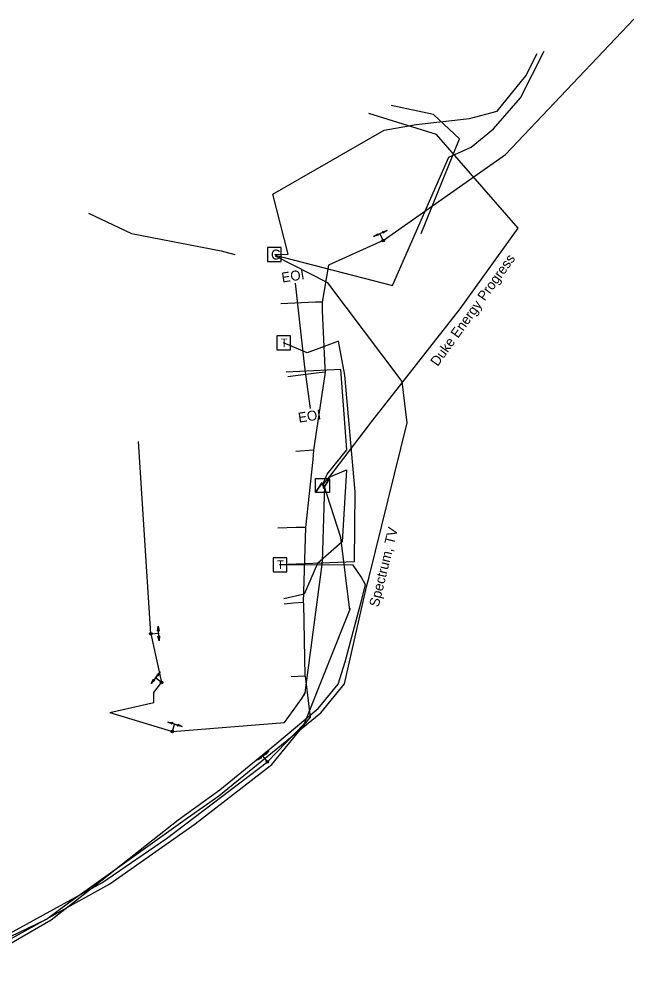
# Model space of a CAD drawing. Extents: x 2070721 to 2083340, y 729290 to 737883.
# Drawn here: x 2080279.4 to 2080526.8, y 734985.4 to 735370.3 of the extents above; entities that cross this region are included whole.
import ezdxf

# ---------------------------------------------------------------- set-up
doc = ezdxf.new("R2010")
doc.units = 0
for name, color, linetype in [('Exist Utilities Gas Change of Service SUE CELL', 7, 'Continuous'), ('Exist Utilities Gas UG Line SUE LOS B', 7, 'Continuous'), ('Exist Utilities Gas UG Line SUE LOS C', 7, 'Continuous'), ('Exist Utilities Other Pole Text', 7, 'Continuous'), ('Exist Utilities Other Unknown UG SUE LOS B', 7, 'Continuous'), ('Exist Utilities Power Change of Service SUE CELL', 7, 'Continuous'), ('Exist Utilities Power Transformer CELL', 7, 'Continuous'), ('Exist Utilities Power UG Cable SUE LOS B', 7, 'Continuous'), ('Exist Utilities Power UG Cable SUE LOS B Text', 7, 'Continuous'), ('Exist Utilities Power UG Cable SUE LOS C', 7, 'Continuous'), ('Exist Utilities Telephone Pedestal CELL', 7, 'Continuous'), ('Exist Utilities Telephone UG Cable SUE LOS C', 7, 'Continuous'), ('Exist Utilities TV Pedestal CELL', 7, 'Continuous'), ('Exist Utilities TV UG Cable SUE LOS C', 7, 'Continuous'), ('Exist Utilities TV UG Cable SUE LOS C Text', 7, 'Continuous'), ('Exist Utilities Water UG Line SUE LOS B', 7, 'Continuous')]:
    doc.layers.add(name, color=color, linetype=linetype)

msp = doc.modelspace()

# ---------------------------------------------------------------- linework, layer by layer
at = {"layer": 'Exist Utilities Gas Change of Service SUE CELL'}
for p, q in [((2080427.49, 735285.18), (2080422.06, 735282.72)), ((2080424.64, 735283.89), (2080427.49, 735285.18)), ((2080425.91, 735281.08), (2080424.64, 735283.89)), ((2080425.91, 735281.08), (2080425.91, 735281.08))]:
    msp.add_line(p, q, dxfattribs=at)
for points in [[(2080422.06, 735282.72), (2080423.71, 735283.85), (2080423.47, 735283.36), (2080423.95, 735283.24)], [(2080427.49, 735285.18), (2080425.84, 735284.06), (2080426.08, 735284.54), (2080425.61, 735284.67)]]:
    msp.add_lwpolyline(points, close=True, dxfattribs=at)
msp.add_circle((2080425.91, 735281.08), 0.517, dxfattribs=at)
at = {"layer": 'Exist Utilities Gas UG Line SUE LOS B'}
msp.add_line((2080397.88, 735196.69), (2080390.75, 735196.19), dxfattribs=at)
for points in [[(2080425.91, 735281.08), (2080403.96, 735271.14), (2080401.43, 735256.34)], [(2080401.43, 735256.34), (2080398.73, 735256.24), (2080384.69, 735255.67)], [(2080401.43, 735256.34), (2080401.37, 735252.76), (2080402.5, 735229.83), (2080402.55, 735228.15)], [(2080402.55, 735228.15), (2080399.01, 735227.73), (2080387.55, 735226.22)], [(2080402.55, 735228.15), (2080397.88, 735196.69)], [(2080397.88, 735196.69), (2080397.62, 735192.92), (2080394.69, 735165.62)], [(2080394.69, 735165.62), (2080390.87, 735165.52), (2080383.56, 735165.33)], [(2080394.7, 735165.52), (2080393.67, 735135.42)], [(2080393.67, 735135.42), (2080389.85, 735135.05), (2080386.03, 735134.67)], [(2080393.67, 735135.42), (2080393.83, 735134.93), (2080394.41, 735105.63), (2080388.9, 735105.46)], [(2080265, 734993.65), (2080268.16, 734995.62), (2080315.96, 735022.08), (2080350.22, 735046.21), (2080381.14, 735070.17), (2080396.65, 735089.25), (2080394.64, 735105.68)]]:
    msp.add_lwpolyline(points, dxfattribs=at)
at = {"layer": 'Exist Utilities Gas UG Line SUE LOS C'}
msp.add_lwpolyline([(2080425.91, 735281.08), (2080475.14, 735315.78), (2080526.82, 735370.27)], dxfattribs=at)
at = {"layer": 'Exist Utilities Other Unknown UG SUE LOS B'}
msp.add_lwpolyline([(2080390.53, 735263.96), (2080394.31, 735230.13), (2080396.49, 735213.47)], dxfattribs=at)
at = {"layer": 'Exist Utilities Power Change of Service SUE CELL'}
for p, q in [((2080335.71, 735119.86), (2080335.33, 735125.81)), ((2080332.43, 735122.8), (2080335.51, 735122.99)), ((2080332.43, 735122.8), (2080332.43, 735122.8)), ((2080335.51, 735122.99), (2080335.71, 735119.86)), ((2080336.21, 735107.48), (2080332.59, 735102.74)), ((2080334.31, 735104.99), (2080336.21, 735107.48)), ((2080336.76, 735103.12), (2080334.31, 735104.99)), ((2080336.76, 735103.12), (2080336.76, 735103.12)), ((2080344.98, 735085.47), (2080339.28, 735087.21)), ((2080341.08, 735083.44), (2080341.98, 735086.39)), ((2080341.08, 735083.44), (2080341.08, 735083.44)), ((2080341.98, 735086.39), (2080344.98, 735085.47)), ((2080379.95, 735075.53), (2080375.2, 735071.92)), ((2080377.45, 735073.63), (2080379.95, 735075.53)), ((2080379.32, 735071.17), (2080377.45, 735073.63)), ((2080379.32, 735071.17), (2080379.32, 735071.17))]:
    msp.add_line(p, q, dxfattribs=at)
for points in [[(2080335.33, 735125.81), (2080335.8, 735123.87), (2080335.43, 735124.27), (2080335.15, 735123.87)], [(2080335.71, 735119.86), (2080335.24, 735121.81), (2080335.61, 735121.41), (2080335.89, 735121.81)], [(2080336.21, 735107.48), (2080335.29, 735105.71), (2080335.27, 735106.25), (2080334.79, 735106.13)], [(2080332.59, 735102.74), (2080333.51, 735104.52), (2080333.53, 735103.97), (2080334.01, 735104.09)], [(2080339.28, 735087.21), (2080341.27, 735086.97), (2080340.76, 735086.76), (2080341.04, 735086.36)], [(2080344.98, 735085.47), (2080343, 735085.72), (2080343.5, 735085.93), (2080343.22, 735086.33)], [(2080379.95, 735075.53), (2080378.59, 735074.06), (2080378.72, 735074.59), (2080378.23, 735074.6)], [(2080375.2, 735071.92), (2080376.56, 735073.39), (2080376.44, 735072.86), (2080376.93, 735072.85)]]:
    msp.add_lwpolyline(points, close=True, dxfattribs=at)
for centre in [(2080332.43, 735122.8), (2080336.76, 735103.12), (2080341.08, 735083.44), (2080379.32, 735071.17)]:
    msp.add_circle(centre, 0.517, dxfattribs=at)
at = {"layer": 'Exist Utilities Power Transformer CELL'}
msp.add_line((2080401.57, 735182.62), (2080401.57, 735182.62), dxfattribs=at)
msp.add_lwpolyline([(2080398.72, 735185.24), (2080404.27, 735185.24), (2080404.27, 735179.68), (2080398.72, 735179.68)], close=True, dxfattribs=at)
for points in [[(2080398.72, 735179.68), (2080401.37, 735183.63), (2080401.99, 735181.42), (2080404.27, 735185.24)], [(2080398.79, 735179.68), (2080401.37, 735183.42), (2080401.95, 735181.24), (2080404.27, 735185.08)]]:
    msp.add_lwpolyline(points, dxfattribs=at)
at = {"layer": 'Exist Utilities Power UG Cable SUE LOS B'}
for points in [[(2080401.57, 735182.62), (2080404.41, 735186.14), (2080421.75, 735208.75), (2080456.92, 735253.65), (2080480.26, 735286.05), (2080447.38, 735323.81), (2080420.2, 735332.31)], [(2080401.57, 735182.62), (2080403.45, 735187.01), (2080411.27, 735196.77), (2080408.82, 735229.21), (2080386.88, 735228.1)], [(2080403.98, 735185.66), (2080411.17, 735188.81), (2080409.41, 735159.72), (2080399.49, 735151.03), (2080394.08, 735138.67), (2080386, 735136.79)], [(2080394.53, 735099.01), (2080401.54, 735151.67), (2080402.47, 735182.6)], [(2080412.55, 735132.28), (2080408.94, 735161.49), (2080401.98, 735182.69)], [(2080412.59, 735132.94), (2080394.09, 735086.48), (2080379.32, 735071.17)], [(2080332.43, 735122.8), (2080336.76, 735103.12)], [(2080341.08, 735083.44), (2080386.18, 735087.05), (2080393.23, 735096.68), (2080394.53, 735099.01), (2080393.88, 735097.84)]]:
    msp.add_lwpolyline(points, dxfattribs=at)
at = {"layer": 'Exist Utilities Power UG Cable SUE LOS C'}
for p, q in [((2080332.43, 735122.8), (2080327.44, 735200.23)), ((2080315.9, 735091.11), (2080341.08, 735083.44))]:
    msp.add_line(p, q, dxfattribs=at)
for points in [[(2080441.2, 735283.91), (2080456.62, 735322.11), (2080446.12, 735331.85), (2080429.09, 735335.47)], [(2080315.9, 735091.11), (2080333.69, 735095.06), (2080333.69, 735099.1), (2080336.76, 735103.12)], [(2080184.91, 735034.97), (2080213.27, 734992.91), (2080223.08, 734985.41), (2080235.33, 734985.41), (2080274.11, 735001.25), (2080312.76, 735022.46), (2080338.71, 735040.35), (2080379.32, 735071.17)]]:
    msp.add_lwpolyline(points, dxfattribs=at)
at = {"layer": 'Exist Utilities Telephone Pedestal CELL'}
for p, q in [((2080385.79, 735239.95), (2080385.79, 735239.95)), ((2080384.31, 735150.56), (2080384.31, 735150.56))]:
    msp.add_line(p, q, dxfattribs=at)
for points in [[(2080383.07, 735237.12), (2080388.66, 735237.12), (2080388.66, 735242.72), (2080383.07, 735242.72), (2080383.07, 735237.12)], [(2080381.59, 735147.74), (2080387.18, 735147.74), (2080387.18, 735153.33), (2080381.59, 735153.33), (2080381.59, 735147.74)]]:
    msp.add_lwpolyline(points, dxfattribs=at)
at = {"layer": 'Exist Utilities Telephone UG Cable SUE LOS C'}
for points in [[(2080384.26, 735150.63), (2080414.34, 735151.9), (2080414.62, 735179.86), (2080410.46, 735226.87), (2080407.97, 735240.56), (2080395.27, 735235.94), (2080385.85, 735239.88)], [(2080258.12, 734995.23), (2080263.29, 734994.32), (2080269.47, 734994.32), (2080277.96, 734999.19), (2080292.29, 735007.6), (2080305.23, 735017.65), (2080343.43, 735047.82), (2080360.16, 735059.94), (2080382.3, 735078.07), (2080399.75, 735092.65), (2080407.82, 735102.46), (2080410.57, 735111.53), (2080417.01, 735135.56), (2080418.86, 735142.51), (2080417.06, 735145.72), (2080413.79, 735150.42), (2080384.27, 735150.47)]]:
    msp.add_lwpolyline(points, dxfattribs=at)
at = {"layer": 'Exist Utilities TV Pedestal CELL'}
msp.add_line((2080382.09, 735275.47), (2080382.09, 735275.47), dxfattribs=at)
msp.add_lwpolyline([(2080379.32, 735272.7), (2080384.87, 735272.7), (2080384.87, 735278.25), (2080379.32, 735278.25), (2080379.32, 735272.7)], dxfattribs=at)
at = {"layer": 'Exist Utilities TV UG Cable SUE LOS C'}
for points in [[(2080382.32, 735275.51), (2080387.67, 735275.64), (2080381.57, 735299.83), (2080426.26, 735325.54), (2080439.21, 735327.78), (2080460.7, 735330.21), (2080471.81, 735333.16), (2080483.32, 735347.41), (2080487.9, 735356.41)], [(2080382.49, 735275.17), (2080429.65, 735262.94), (2080452.36, 735314.62), (2080461.36, 735318.73), (2080470.3, 735326.03), (2080481.2, 735338.62), (2080490.75, 735357.43)], [(2080420.28, 735145.67), (2080435.53, 735207.68), (2080433.57, 735224.41), (2080403.63, 735264.05), (2080382.55, 735274.81)], [(2080359.81, 735057.53), (2080400.79, 735090.94), (2080410.35, 735102.61), (2080419.18, 735141.68), (2080420.28, 735145.67)], [(2080259.06, 735072.37), (2080251.03, 735055.15), (2080258.34, 735010.88), (2080268.58, 734997.41), (2080290.37, 735007.91), (2080299.29, 735014.42), (2080347.12, 735048.66), (2080359.81, 735057.53)]]:
    msp.add_lwpolyline(points, dxfattribs=at)
at = {"layer": 'Exist Utilities Water UG Line SUE LOS B'}
msp.add_lwpolyline([(2080307.31, 735292.11), (2080324.7, 735284.01), (2080360.73, 735276.97), (2080366.17, 735275.47)], dxfattribs=at)

# ---------------------------------------------------------------- texts
at = {"layer": 'Exist Utilities Other Pole Text'}
for p in [(2080385.35, 735264.16), (2080392.03, 735207.75)]:
    msp.add_text('EOI', height=4, rotation=8.9445, dxfattribs=at).set_placement(p)
at = {"layer": 'Exist Utilities Power UG Cable SUE LOS B Text'}
msp.add_text('Duke Energy Progress', height=4, rotation=54.2195, dxfattribs=at).set_placement((2080447.83, 735230.18))
at = {"layer": 'Exist Utilities Telephone Pedestal CELL'}
for p in [(2080384.66, 735238.24), (2080383.18, 735148.85)]:
    msp.add_text('T', height=3.42, dxfattribs=at).set_placement(p)
at = {"layer": 'Exist Utilities TV Pedestal CELL'}
msp.add_text('C', height=4, dxfattribs=at).set_placement((2080380.78, 735273.47))
at = {"layer": 'Exist Utilities TV UG Cable SUE LOS C Text'}
msp.add_text('Spectrum, TV ', height=4, rotation=76.1827, dxfattribs=at).set_placement((2080424.08, 735133.32))

doc.saveas('drawing.dxf')
